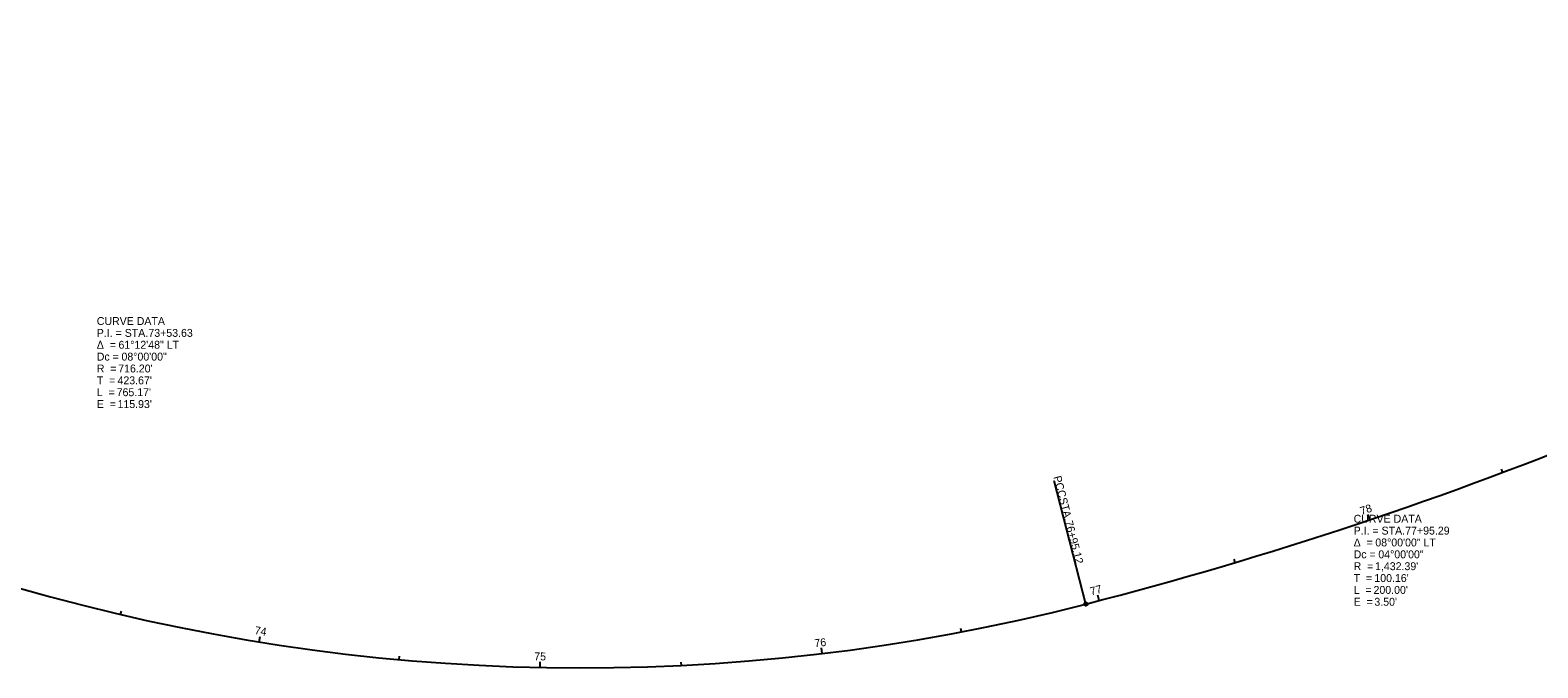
# Model space of a CAD drawing. Extents: x 2202679 to 2204820, y 634848 to 638099.
# Drawn here: x 2203213 to 2203747, y 634848 to 635074 of the extents above; entities that cross this region are included whole.
import ezdxf

# ---------------------------------------------------------------- set-up
doc = ezdxf.new("R2010")
doc.units = 0
for name, color, linetype in [('_CIVIL_CONSTRUCTION', 7, 'Continuous'), ('RW_X_CL', 7, 'Continuous'), ('RW_X_CL_100_Cardinal_Points', 7, 'Continuous'), ('SC_Scratch1', 7, 'Continuous')]:
    doc.layers.add(name, color=color, linetype=linetype)

msp = doc.modelspace()

# ---------------------------------------------------------------- linework, layer by layer
at = {"layer": 'RW_X_CL'}
msp.add_line((2203586.84, 634870.62), (2203575.63, 634914.2), dxfattribs=at)
msp.add_circle((2203586.84, 634870.62), 0.6, dxfattribs=at)
at = {"layer": 'RW_X_CL_100_Cardinal_Points'}
for p, q in [((2203734.46, 634917.24), (2203734.03, 634918.36)), ((2203687.36, 634900.45), (2203686.72, 634902.34)), ((2203639.71, 634885.31), (2203639.37, 634886.46)), ((2203591.56, 634871.84), (2203591.06, 634873.78)), ((2203245.07, 634866.89), (2203245.34, 634868.06)), ((2203542.82, 634860.76), (2203542.59, 634861.93)), ((2203294.11, 634857.19), (2203294.43, 634859.17)), ((2203343.71, 634850.95), (2203343.82, 634852.14)), ((2203493.42, 634853.09), (2203493.18, 634855.08)), ((2203393.62, 634848.17), (2203393.66, 634850.17)), ((2203443.61, 634848.89), (2203443.55, 634850.09))]:
    msp.add_line(p, q, dxfattribs=at)
at = {"layer": 'SC_Scratch1'}
for centre, radius, start, end in [((2203408.37, 635564.22), 716.2, 223.21683, 284.43016), ((2203408.37, 635564.22), 716.2, 223.21683, 284.43016), ((2203408.37, 635564.22), 716.2, 223.21683, 284.43016), ((2203229.89, 636257.82), 1432.39, 284.43016, 292.43016), ((2203229.89, 636257.82), 1432.39, 284.43016, 292.43016)]:
    msp.add_arc(centre, radius, start, end, dxfattribs=at)

# ---------------------------------------------------------------- texts
at = {"layer": '_CIVIL_CONSTRUCTION'}
for s, p in [('CURVE DATA', (2203236.63, 634969.41)), ('P.I. = STA. ', (2203236.63, 634965.21)), ('73+53.63', (2203254.9, 634965.21)), ('Δ  = ', (2203236.63, 634961.01)), ('61°12\'48" LT', (2203244.31, 634961.01)), ('Dc = ', (2203236.63, 634956.81)), ('08°00\'00"', (2203245.37, 634956.81)), ('R  = ', (2203236.63, 634952.61)), ("716.20'", (2203244.22, 634952.61)), ('T  = ', (2203236.63, 634948.41)), ('L  = ', (2203236.63, 634944.21)), ("765.17'", (2203243.67, 634944.21)), ("423.67'", (2203243.97, 634948.41)), ('E  = ', (2203236.63, 634940.01)), ("115.93'", (2203243.97, 634940.01)), ('CURVE DATA', (2203681.64, 634899.41)), ('Δ  = ', (2203681.64, 634891.01)), ('P.I. = STA. ', (2203681.64, 634895.21)), ('08°00\'00" LT', (2203689.31, 634891.01)), ('77+95.29', (2203699.9, 634895.21)), ('Dc = ', (2203681.64, 634886.81)), ('04°00\'00"', (2203690.38, 634886.81)), ('R  = ', (2203681.64, 634882.61)), ("1,432.39'", (2203689.22, 634882.61)), ('T  = ', (2203681.64, 634878.41)), ("100.16'", (2203688.97, 634878.41)), ('L  = ', (2203681.64, 634874.21)), ('E  = ', (2203681.64, 634870.01)), ("200.00'", (2203688.68, 634874.21)), ("3.50'", (2203688.98, 634870.01))]:
    msp.add_text(s, height=2.8, dxfattribs=at).set_placement(p)
at = {"layer": 'RW_X_CL'}
for s, p in [('PCC', (2203575.31, 634915.62)), (' STA. ', (2203577.02, 634908.95)), ('76+95.12', (2203579.38, 634899.79))]:
    msp.add_text(s, height=2.8, rotation=284.4302, dxfattribs=at).set_placement(p)
at = {"layer": 'RW_X_CL_100_Cardinal_Points'}
for s, rotation, p in [('78', 18.6252, (2203684.46, 634902.11)), ('77', 14.6252, (2203588.71, 634873.68)), ('74', 350.8203, (2203292.38, 634860.01)), ('76', 6.8203, (2203490.9, 634855.31)), ('75', 358.8203, (2203391.49, 634850.72))]:
    msp.add_text(s, height=2.8, rotation=rotation, dxfattribs=at).set_placement(p)

doc.saveas('drawing.dxf')
